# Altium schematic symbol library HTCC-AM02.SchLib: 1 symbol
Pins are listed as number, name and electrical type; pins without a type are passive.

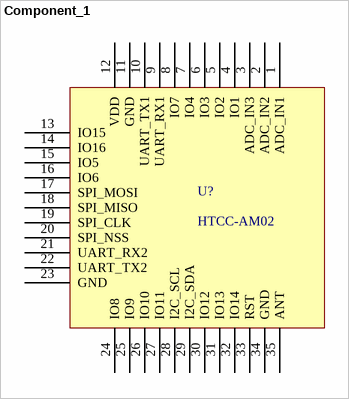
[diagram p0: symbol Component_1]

## Component_1
designator U?, comment HTCC-AM02
pins: 1 ADC_IN1, 2 ADC_IN2, 3 ADC_IN3, 4 IO1, 5 IO2, 6 IO3, 7 IO4, 8 IO7, 9 UART_RX1, 10 UART_TX1, 11 GND, 12 VDD, 13 IO15, 14 IO16, 15 IO5, 16 IO6, 17 SPI_MOSI, 18 SPI_MISO, 19 SPI_CLK, 20 SPI_NSS, 21 UART_RX2, 22 UART_TX2, 23 GND, 24 IO8, 25 IO9, 26 IO10, 27 IO11, 28 I2C_SCL, 29 I2C_SDA, 30 IO12, 31 IO13, 32 IO14, 33 RST, 34 GND, 35 ANT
